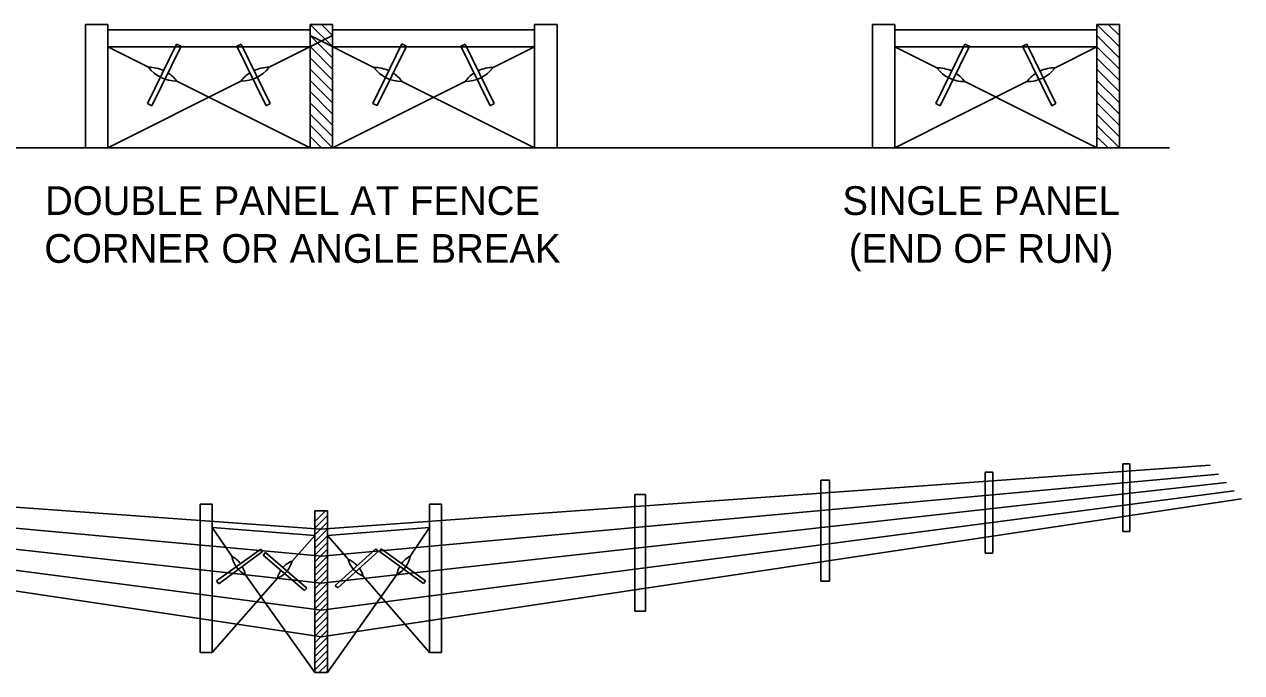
# Model space of a CAD drawing. Extents: x 49991.4 to 50021, y 49987.6 to 50011.4.
# Drawn here: x 50010.385 to 50012.929, y 49992.148 to 49993.502 of the extents above; entities that cross this region are included whole.
import ezdxf

# ---------------------------------------------------------------- set-up
doc = ezdxf.new("R2010")
doc.units = 0
doc.layers.add('Level 1', color=7, linetype='Continuous')
doc.layers.add('Level 2', color=7, linetype='Continuous')

msp = doc.modelspace()

# ---------------------------------------------------------------- linework, layer by layer
at = {"layer": 'Level 1'}
for p, q in [((50010.5127, 49993.5021), (50010.5127, 49993.2439)), ((50010.5596, 49993.5021), (50010.5127, 49993.5021)), ((50010.5596, 49993.2439), (50010.5596, 49993.5021)), ((50010.9822, 49993.5021), (50010.9822, 49993.2439)), ((50010.9822, 49993.5021), (50011.0291, 49993.5021)), ((50011.0291, 49993.4556), (50010.9825, 49993.5021)), ((50011.0291, 49993.479), (50011.0059, 49993.5021)), ((50011.0291, 49993.2439), (50011.0291, 49993.5021)), ((50011.4516, 49993.2439), (50011.4516, 49993.5021)), ((50011.4516, 49993.5021), (50011.4985, 49993.5021)), ((50011.4985, 49993.5021), (50011.4985, 49993.2439)), ((50012.2042, 49993.5021), (50012.1573, 49993.5021)), ((50012.1573, 49993.5021), (50012.1573, 49993.2439)), ((50012.2042, 49993.2439), (50012.2042, 49993.5021)), ((50012.6736, 49993.5021), (50012.6267, 49993.5021)), ((50012.6267, 49993.5021), (50012.6267, 49993.2439)), ((50012.6736, 49993.4552), (50012.6267, 49993.5021)), ((50012.6736, 49993.4786), (50012.6502, 49993.5021)), ((50012.6736, 49993.2439), (50012.6736, 49993.5021)), ((50010.9822, 49993.4904), (50010.5596, 49993.4904)), ((50010.8968, 49993.4125), (50011.0291, 49993.4786)), ((50011.0291, 49993.4321), (50010.9822, 49993.4789)), ((50010.9822, 49993.4786), (50011.1155, 49993.412)), ((50011.0291, 49993.4904), (50011.4516, 49993.4904)), ((50012.6267, 49993.4904), (50012.2042, 49993.4904)), ((50012.6736, 49993.4317), (50012.6267, 49993.4786)), ((50010.9822, 49993.4552), (50010.5596, 49993.4552)), ((50010.645, 49993.4125), (50010.5596, 49993.4552)), ((50010.6427, 49993.3365), (50010.7034, 49993.4609)), ((50010.6513, 49993.3321), (50010.7126, 49993.4562)), ((50010.7034, 49993.4609), (50010.7126, 49993.4562)), ((50010.8384, 49993.4609), (50010.8292, 49993.4562)), ((50010.8905, 49993.3321), (50010.8292, 49993.4562)), ((50010.8991, 49993.3365), (50010.8384, 49993.4609)), ((50011.0291, 49993.4086), (50010.9822, 49993.4555)), ((50011.0291, 49993.4552), (50011.4516, 49993.4552)), ((50011.1137, 49993.3368), (50011.1744, 49993.4612)), ((50011.1224, 49993.3324), (50011.1835, 49993.4565)), ((50011.1744, 49993.4612), (50011.1835, 49993.4565)), ((50011.3065, 49993.4609), (50011.2973, 49993.4562)), ((50011.3584, 49993.3321), (50011.2973, 49993.4562)), ((50011.3671, 49993.3365), (50011.3065, 49993.4609)), ((50011.3651, 49993.412), (50011.4516, 49993.4552)), ((50012.6267, 49993.4552), (50012.2042, 49993.4552)), ((50012.2918, 49993.4114), (50012.2042, 49993.4552)), ((50012.2901, 49993.3366), (50012.3508, 49993.461)), ((50012.2987, 49993.3322), (50012.36, 49993.4563)), ((50012.3508, 49993.461), (50012.36, 49993.4563)), ((50012.4801, 49993.461), (50012.4709, 49993.4563)), ((50012.5322, 49993.3322), (50012.4709, 49993.4563)), ((50012.5408, 49993.3366), (50012.4801, 49993.461)), ((50012.5391, 49993.4114), (50012.6267, 49993.4552)), ((50012.6736, 49993.4082), (50012.6267, 49993.4552)), ((50011.0291, 49993.3852), (50010.9822, 49993.432)), ((50012.6736, 49993.3848), (50012.6267, 49993.4317)), ((50011.0291, 49993.3617), (50010.9822, 49993.4085)), ((50012.6736, 49993.3613), (50012.6267, 49993.4082)), ((50010.5596, 49993.2439), (50010.8379, 49993.3835)), ((50010.9822, 49993.2439), (50010.7038, 49993.3835)), ((50011.0291, 49993.3382), (50010.9822, 49993.3851)), ((50011.0291, 49993.2439), (50011.3062, 49993.383)), ((50011.1743, 49993.383), (50011.4516, 49993.2439)), ((50012.2042, 49993.2439), (50012.4803, 49993.3824)), ((50012.6267, 49993.2439), (50012.3506, 49993.3824)), ((50012.6736, 49993.3378), (50012.6267, 49993.3848)), ((50011.0291, 49993.3148), (50010.9822, 49993.3616)), ((50012.6736, 49993.3144), (50012.6267, 49993.3613)), ((50010.6513, 49993.3321), (50010.6427, 49993.3365)), ((50010.8905, 49993.3321), (50010.8991, 49993.3365)), ((50011.0291, 49993.2913), (50010.9822, 49993.3381)), ((50011.1224, 49993.3324), (50011.1137, 49993.3368)), ((50011.3671, 49993.3365), (50011.3584, 49993.3321)), ((50012.2987, 49993.3322), (50012.2901, 49993.3366)), ((50012.5322, 49993.3322), (50012.5408, 49993.3366)), ((50012.6736, 49993.2909), (50012.6267, 49993.3378)), ((50011.0291, 49993.2678), (50010.9822, 49993.3147)), ((50012.6736, 49993.2674), (50012.6267, 49993.3144)), ((50011.0291, 49993.2443), (50010.9822, 49993.2912)), ((50012.6736, 49993.2439), (50012.6267, 49993.2909)), ((50011.0059, 49993.2439), (50010.9822, 49993.2677)), ((50012.6502, 49993.2439), (50012.6267, 49993.2674)), ((50009.2569, 49993.2439), (50012.7785, 49993.2439)), ((50011.0069, 49992.3908), (50009.144, 49992.5611)), ((50011.0049, 49992.4472), (50009.1565, 49992.5802)), ((50011.0049, 49992.4472), (50012.863, 49992.581)), ((50011.0069, 49992.3908), (50012.8805, 49992.5623)), ((50012.3933, 49992.5662), (50012.4091, 49992.5662)), ((50012.3933, 49992.3972), (50012.3933, 49992.5662)), ((50012.4091, 49992.3972), (50012.4091, 49992.5662)), ((50012.6805, 49992.5836), (50012.695, 49992.5836)), ((50012.6805, 49992.4427), (50012.6805, 49992.5836)), ((50012.695, 49992.4427), (50012.695, 49992.5836)), ((50011.0057, 49992.3347), (50009.1319, 49992.5427)), ((50011.0057, 49992.3347), (50012.8971, 49992.5446)), ((50012.0498, 49992.5498), (50012.0678, 49992.5498)), ((50012.0498, 49992.339), (50012.0498, 49992.5498)), ((50012.0678, 49992.339), (50012.0678, 49992.5498)), ((50011.0061, 49992.2782), (50009.1199, 49992.5244)), ((50011.0061, 49992.2782), (50012.9134, 49992.5272)), ((50011.0061, 49992.2222), (50012.929, 49992.5106)), ((50011.6612, 49992.52), (50011.683, 49992.52)), ((50011.6612, 49992.2759), (50011.6612, 49992.52)), ((50011.683, 49992.2759), (50011.683, 49992.52)), ((50011.0061, 49992.2222), (50009.1083, 49992.5067)), ((50010.7527, 49992.4998), (50010.7777, 49992.4998)), ((50010.7527, 49992.1899), (50010.7527, 49992.4998)), ((50010.7777, 49992.1899), (50010.7777, 49992.4998)), ((50011.019, 49992.4857), (50010.9922, 49992.4857)), ((50010.9922, 49992.4635), (50011.0147, 49992.4857)), ((50010.9922, 49992.4857), (50010.9922, 49992.1477)), ((50011.019, 49992.1477), (50011.019, 49992.4857)), ((50011.2317, 49992.4998), (50011.2567, 49992.4998)), ((50011.2317, 49992.1899), (50011.2317, 49992.4998)), ((50011.2567, 49992.1899), (50011.2567, 49992.4998)), ((50010.9922, 49992.4494), (50011.019, 49992.4759)), ((50010.9922, 49992.4353), (50011.019, 49992.4618)), ((50010.7777, 49992.451), (50010.9922, 49992.4341)), ((50010.7777, 49992.451), (50010.8189, 49992.3907)), ((50010.9922, 49992.4341), (50010.9447, 49992.3808)), ((50010.9922, 49992.4212), (50011.019, 49992.4477)), ((50010.9922, 49992.4071), (50011.019, 49992.4336)), ((50011.019, 49992.4339), (50011.2317, 49992.4507)), ((50011.019, 49992.4339), (50011.0617, 49992.3844)), ((50011.1914, 49992.391), (50011.2317, 49992.4507)), ((50012.6805, 49992.4427), (50012.695, 49992.4427)), ((50010.9922, 49992.393), (50011.019, 49992.4195)), ((50010.7869, 49992.3392), (50010.8791, 49992.4059)), ((50010.7914, 49992.3334), (50010.8829, 49992.4005)), ((50010.8829, 49992.4005), (50010.8791, 49992.4059)), ((50010.8844, 49992.3932), (50010.8889, 49992.3986)), ((50010.9708, 49992.319), (50010.8844, 49992.3932)), ((50010.9756, 49992.3242), (50010.8889, 49992.3986)), ((50010.9922, 49992.3789), (50011.019, 49992.4054)), ((50010.9922, 49992.3648), (50011.019, 49992.3913)), ((50011.035, 49992.3298), (50011.12, 49992.406)), ((50011.04, 49992.3246), (50011.1243, 49992.4009)), ((50011.1243, 49992.4009), (50011.12, 49992.406)), ((50011.1273, 49992.4011), (50011.1311, 49992.4065)), ((50011.2193, 49992.3338), (50011.1273, 49992.4011)), ((50011.2238, 49992.3395), (50011.1311, 49992.4065)), ((50012.3933, 49992.3972), (50012.4091, 49992.3972)), ((50010.9922, 49992.3507), (50011.019, 49992.3772)), ((50010.9922, 49992.3366), (50011.019, 49992.3631)), ((50010.9139, 49992.3449), (50010.7777, 49992.1899)), ((50010.7914, 49992.3334), (50010.7869, 49992.3392)), ((50010.8466, 49992.3524), (50010.9922, 49992.1477)), ((50010.9922, 49992.3225), (50011.019, 49992.349)), ((50010.9922, 49992.3084), (50011.019, 49992.3349)), ((50011.019, 49992.1477), (50011.1637, 49992.3527)), ((50011.0933, 49992.3491), (50011.2317, 49992.1899)), ((50011.2193, 49992.3338), (50011.2238, 49992.3395)), ((50012.0498, 49992.339), (50012.0678, 49992.339)), ((50010.9708, 49992.319), (50010.9756, 49992.3242)), ((50010.9922, 49992.2943), (50011.019, 49992.3208)), ((50010.9922, 49992.2802), (50011.019, 49992.3067)), ((50011.04, 49992.3246), (50011.035, 49992.3298)), ((50010.9922, 49992.2661), (50011.019, 49992.2926)), ((50010.9922, 49992.252), (50011.019, 49992.2785)), ((50010.9922, 49992.2379), (50011.019, 49992.2644)), ((50011.6612, 49992.2759), (50011.683, 49992.2759)), ((50010.9922, 49992.2238), (50011.019, 49992.2503)), ((50010.9922, 49992.2097), (50011.019, 49992.2362)), ((50010.9922, 49992.1956), (50011.019, 49992.2221)), ((50010.9922, 49992.1815), (50011.019, 49992.208)), ((50010.7527, 49992.1899), (50010.7777, 49992.1899)), ((50010.9922, 49992.1674), (50011.019, 49992.1939)), ((50010.9922, 49992.1533), (50011.019, 49992.1798)), ((50011.2317, 49992.1899), (50011.2567, 49992.1899)), ((50011.0008, 49992.1477), (50011.019, 49992.1657)), ((50010.9922, 49992.1477), (50011.019, 49992.1477)), ((50011.015, 49992.1477), (50011.019, 49992.1516))]:
    msp.add_line(p, q, dxfattribs=at)
for centre, radius, start, end in [((50010.7031, 49993.4563), 0.0728, 216.9715, 270.5589), ((50010.6457, 49993.3397), 0.0728, 64.9913, 90.5589), ((50010.6457, 49993.3397), 0.0728, 36.9715, 57.0704), ((50010.8387, 49993.4563), 0.0728, 269.4411, 323.0285), ((50010.8961, 49993.3397), 0.0728, 122.9296, 143.0285), ((50010.8961, 49993.3397), 0.0728, 89.4411, 115.0087), ((50011.1736, 49993.4558), 0.0728, 216.9715, 270.5589), ((50011.1162, 49993.3392), 0.0728, 64.8879, 90.5589), ((50011.1162, 49993.3392), 0.0728, 36.9715, 57.0035), ((50011.3069, 49993.4558), 0.0728, 269.4411, 323.0285), ((50011.3644, 49993.3392), 0.0728, 122.8827, 143.0285), ((50011.3644, 49993.3392), 0.0728, 89.4411, 114.9637), ((50012.3499, 49993.4552), 0.0728, 216.9715, 270.5589), ((50012.2925, 49993.3386), 0.0728, 64.982, 90.5589), ((50012.481, 49993.4552), 0.0728, 269.4411, 323.0285), ((50012.5384, 49993.3386), 0.0728, 89.4411, 115.018), ((50012.2925, 49993.3386), 0.0728, 36.9715, 57.0655), ((50012.5384, 49993.3386), 0.0728, 122.9345, 143.0285), ((50010.8707, 49992.399), 0.0524, 189.0978, 242.6852), ((50010.7949, 49992.3441), 0.0524, 36.6416, 62.6852), ((50011.1124, 49992.398), 0.0524, 195.0597, 248.6626), ((50011.0427, 49992.3355), 0.0524, 42.8063, 68.6626), ((50011.1397, 49992.3993), 0.0524, 297.3084, 350.9022), ((50011.2155, 49992.3444), 0.0524, 117.3148, 143.1447), ((50010.7949, 49992.3441), 0.0524, 9.0978, 29.0616), ((50010.8938, 49992.3933), 0.0524, 292.5721, 346.1595), ((50010.9648, 49992.3324), 0.0524, 146.1566, 166.1595), ((50010.9648, 49992.3324), 0.0524, 112.5721, 138.463), ((50011.0427, 49992.3355), 0.0524, 15.0597, 35.225), ((50011.2155, 49992.3444), 0.0524, 150.7338, 170.9113)]:
    msp.add_arc(centre, radius, start, end, dxfattribs=at)

# ---------------------------------------------------------------- texts
at = {"layer": 'Level 2'}
for s, p in [('DOUBLE PANEL AT FENCE', (50010.4286, 49993.1039)), ('SINGLE PANEL', (50012.0947, 49993.1039)), ('CORNER OR ANGLE BREAK', (50010.4269, 49993.0039)), ('(END OF RUN)', (50012.1082, 49993.0039))]:
    msp.add_text(s, height=0.06, dxfattribs=at).set_placement(p)

doc.saveas('drawing.dxf')
